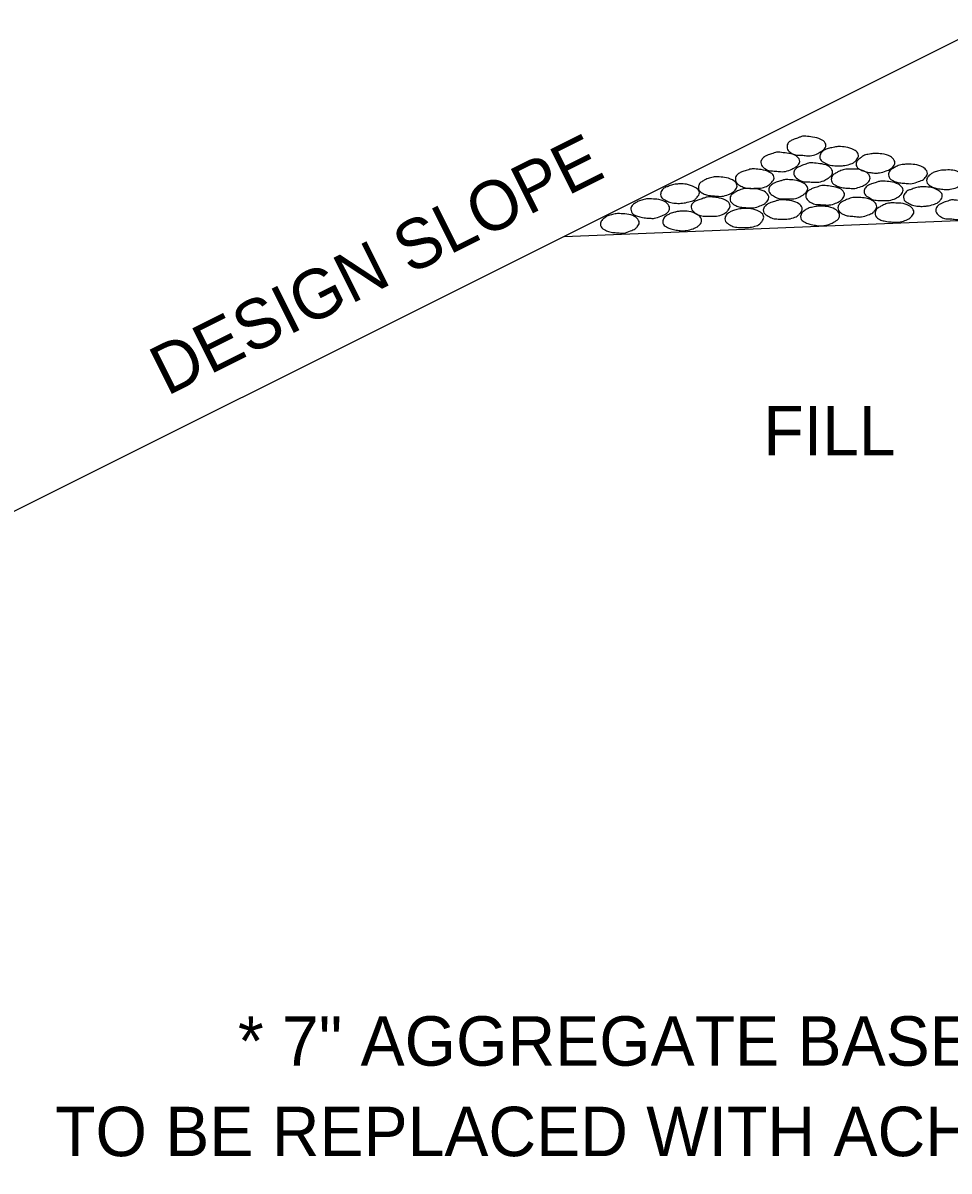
# Model space of a CAD drawing. Extents: x 438659 to 573674, y 10724 to 98600.
# Drawn here: x 493788 to 497162, y 66360 to 70542 of the extents above; entities that cross this region are included whole.
import ezdxf

# ---------------------------------------------------------------- set-up
doc = ezdxf.new("R2010")
doc.units = 0
doc.layers.add('T_Vehicle Path Rt', color=7, linetype='Continuous')

msp = doc.modelspace()

# ---------------------------------------------------------------- linework, layer by layer
at = {"layer": 'T_Vehicle Path Rt'}
for p, q in [((493589.4, 68680.3), (497314.8, 70541.7)), ((495759.4, 69764.5), (503294.2, 70064.7))]:
    msp.add_line(p, q, dxfattribs=at)
for points in [[(496640.5, 70128.9), (496665.2, 70126), (496695.1, 70117.8), (496711.1, 70104.4), (496713.3, 70095.4), (496705.7, 70080.4), (496696, 70073.4), (496679.1, 70063.9), (496655.8, 70058.1), (496642.9, 70058.1), (496624.9, 70060), (496603.3, 70061.2), (496588.5, 70067.5), (496573.7, 70081.4), (496571.8, 70090.6), (496576.2, 70104.7), (496587.1, 70113.4), (496597.8, 70118.5), (496614.5, 70124.1), (496624.2, 70128.2), (496640.5, 70128.9)], [(496760.6, 70091.6), (496786.1, 70089.6), (496815.4, 70079.9), (496830, 70067), (496832.2, 70059.5), (496824.6, 70043), (496817.6, 70035.3), (496800.1, 70026.8), (496777.1, 70022.2), (496764.2, 70021.2), (496745.5, 70021.7), (496724.2, 70025.1), (496709.1, 70032.3), (496693.4, 70044), (496690.9, 70053.9), (496695.3, 70067), (496707.4, 70078), (496717.6, 70082.8), (496734.9, 70087.4), (496745.1, 70089.6), (496760.6, 70091.6)], [(496545.6, 70070.9), (496571.1, 70067.5), (496600, 70060.5), (496616, 70046.4), (496618.4, 70037.7), (496610.4, 70022.4), (496601.2, 70015.8), (496584.4, 70006.9), (496560.4, 70000.1), (496548.3, 70000.1), (496529.8, 70002.3), (496508.7, 70003.5), (496493.2, 70010), (496479.1, 70023.6), (496476.4, 70033.1), (496481.5, 70046.7), (496492.7, 70056.4), (496503.4, 70061.2), (496519.9, 70066.6), (496529.8, 70070), (496545.6, 70070.9)], [(496892.8, 70065.8), (496917.6, 70065.1), (496948.4, 70055.4), (496962.5, 70040.8), (496965.1, 70032.3), (496956.9, 70016.8), (496948.9, 70010), (496932.4, 70002.7), (496908.1, 69996), (496895, 69995), (496876.6, 69996.7), (496856.4, 70000.1), (496840.7, 70006.4), (496825.9, 70018.3), (496823.4, 70027.5), (496828.3, 70041.3), (496839.4, 70050.1), (496849.9, 70058.1), (496866.6, 70063.2), (496877.1, 70065.1), (496892.8, 70065.8)], [(496453.1, 70010), (496478.1, 70007.6), (496507.3, 69998.4), (496522.5, 69986), (496524.7, 69976.8), (496516.5, 69962), (496507.7, 69953.7), (496492.5, 69944.8), (496468.4, 69939.7), (496456.1, 69939.7), (496436.9, 69939.2), (496416, 69942.6), (496400, 69949.8), (496385.2, 69963.2), (496383.5, 69971.2), (496387.9, 69986.5), (496398.5, 69995), (496410.2, 70000.1), (496427.7, 70005.4), (496436.9, 70008.6), (496453.1, 70010)], [(496666.2, 70031.9), (496690.9, 70029), (496721, 70021.7), (496735.6, 70007.1), (496737.8, 69998.9), (496730.5, 69983.3), (496721.5, 69976.5), (496705.7, 69967.3), (496682, 69961.5), (496669.1, 69961.5), (496650.2, 69963.2), (496629.3, 69964.2), (496614, 69971.4), (496599, 69984.8), (496596.3, 69994), (496600.9, 70008.1), (496612.6, 70016.6), (496623.7, 70021.7), (496640.5, 70028), (496650.2, 70031.4), (496666.2, 70031.9)], [(496802.6, 70009.5), (496827.3, 70008.6), (496857.9, 69999.3), (496872, 69985), (496874.1, 69976.5), (496866.6, 69961), (496859.3, 69954.2), (496841.6, 69946), (496818.6, 69939.2), (496805.7, 69939.2), (496786.3, 69940.4), (496766.2, 69943.8), (496750.6, 69949.4), (496735.1, 69962.5), (496733.2, 69971.9), (496737, 69986), (496748.9, 69994.5), (496759.9, 70000.3), (496776.6, 70007.1), (496786.3, 70009.3), (496802.6, 70009.5)], [(497011.7, 70027.3), (497037.5, 70025.8), (497066.6, 70016.6), (497080.9, 70002.7), (497083.6, 69993.5), (497075.3, 69978.7), (497068.8, 69971.9), (497051, 69964.2), (497027.3, 69956.4), (497014.9, 69956.4), (496996.2, 69958.1), (496976.3, 69960.5), (496959.3, 69966.3), (496943.8, 69979.7), (496941.6, 69988.9), (496946.2, 70003), (496957.4, 70011.7), (496969, 70018.3), (496985.8, 70024.6), (496996.2, 70026.3), (497011.7, 70027.3)], [(497150.8, 70006.1), (497175.8, 70005.4), (497204.6, 69995), (497219.2, 69982.1), (497221.6, 69973.4), (497214.6, 69957.1), (497206.1, 69950.6), (497189.8, 69942.6), (497165.6, 69936), (497153.2, 69934.8), (497134.8, 69936.7), (497113.9, 69939.9), (497097.6, 69946), (497082.6, 69958.1), (497080.2, 69967.8), (497085, 69981.4), (497095.9, 69991.3), (497107.6, 69997.9), (497124.3, 70003), (497135, 70005.4), (497150.8, 70006.1)], [(496180.9, 69955.4), (496205.9, 69954.2), (496235, 69943.8), (496250.5, 69931.6), (496252.7, 69923.6), (496244.2, 69907.1), (496236.9, 69898.9), (496219.5, 69891.6), (496196.7, 69886), (496184.5, 69884.8), (496164.6, 69885.3), (496143.3, 69889.2), (496128.5, 69896.2), (496113.4, 69908.1), (496111.2, 69917.3), (496115.6, 69931.6), (496126.8, 69941.6), (496138.2, 69946.5), (496154.9, 69952), (496164.4, 69954.2), (496180.9, 69955.4)], [(496318.7, 69980.9), (496344.4, 69979.2), (496373.3, 69970), (496388.1, 69955.9), (496389.8, 69947.4), (496382.5, 69932.6), (496374.5, 69925.3), (496358, 69916.8), (496334.2, 69910.3), (496321.6, 69910.3), (496302.9, 69912.2), (496282.8, 69914.2), (496266.5, 69920), (496251, 69933.3), (496249.1, 69943.1), (496253.2, 69956.4), (496264.4, 69965.4), (496275.5, 69971.9), (496293.2, 69977.8), (496302.9, 69980.2), (496318.7, 69980.9)], [(496574.2, 69971.4), (496599.5, 69969), (496629.8, 69960), (496644.8, 69946.5), (496647.5, 69938.2), (496639.5, 69922.7), (496631.3, 69916.1), (496613.5, 69905.9), (496590.7, 69900.8), (496577.6, 69900.8), (496558.7, 69901.3), (496538.1, 69903.5), (496522.5, 69911.5), (496507.7, 69923.9), (496505.6, 69933.8), (496510.4, 69947.4), (496521.8, 69956.4), (496532.5, 69961.5), (496548.3, 69966.3), (496558.5, 69970), (496574.2, 69971.4)], [(496923.4, 69965.6), (496948.9, 69963.4), (496977.3, 69954.2), (496992.1, 69940.9), (496994.3, 69933.1), (496987.2, 69916.6), (496979, 69909.6), (496962, 69900.3), (496938, 69894.8), (496925.8, 69894.8), (496907.4, 69895.3), (496886.5, 69897.7), (496870.5, 69905.4), (496854.7, 69917.8), (496852.3, 69928.5), (496857.4, 69941.6), (496868.6, 69950.8), (496879.7, 69955.4), (496896.5, 69961), (496908.1, 69964.4), (496923.4, 69965.6)], [(496434, 69938.7), (496458.2, 69937), (496488.6, 69928.5), (496503.6, 69913.9), (496505.6, 69905.4), (496498, 69890.4), (496490.5, 69883.4), (496473, 69875.1), (496450, 69868.3), (496436.4, 69868.3), (496417.5, 69869.5), (496396.9, 69872.4), (496381.6, 69878.3), (496366.3, 69891.6), (496364.1, 69900.8), (496368.7, 69914.7), (496380.1, 69923.6), (496391, 69929.7), (496407.8, 69936), (496417.5, 69938.2), (496434, 69938.7)], [(496710.4, 69949.8), (496735.1, 69946.5), (496764.2, 69938.7), (496779, 69924.6), (496781.2, 69916.1), (496773.4, 69900.8), (496766.2, 69893.8), (496748.9, 69884.8), (496725.6, 69878.8), (496712.5, 69878.8), (496694.1, 69880), (496672.7, 69881.7), (496656.7, 69889.2), (496642.2, 69902.3), (496640, 69912), (496643.9, 69925.1), (496655.3, 69934.1), (496666.9, 69939.7), (496684.4, 69945.2), (496694.1, 69948.9), (496710.4, 69949.8)], [(497066.1, 69944.8), (497090.8, 69943.5), (497120.7, 69933.3), (497135.2, 69920.5), (497137.4, 69912.7), (497129.9, 69895.7), (497122.6, 69888.5), (497104.9, 69880.4), (497081.6, 69875.1), (497069.2, 69873.9), (497050.3, 69874.1), (497029, 69878), (497013.9, 69885.3), (496998.9, 69896.7), (496996.2, 69907.1), (497000.8, 69920.5), (497011.7, 69930.9), (497023.6, 69935.5), (497040.1, 69940.9), (497049.8, 69943.5), (497066.1, 69944.8)], [(496072.4, 69900.8), (496097.2, 69899.4), (496127.3, 69890.6), (496141.8, 69875.8), (496144, 69867.8), (496136.7, 69851.8), (496128.7, 69845.3), (496112, 69838), (496088.4, 69830.2), (496075.6, 69830.2), (496056.2, 69831.7), (496035.5, 69835.3), (496020, 69840.4), (496005, 69853.3), (496003, 69863.2), (496007.1, 69876.8), (496019, 69885.8), (496030.2, 69892.3), (496046.7, 69897.9), (496056.2, 69900.3), (496072.4, 69900.8)], [(496294.2, 69908.1), (496318.5, 69905.4), (496347.1, 69896.2), (496362.2, 69883.4), (496364.1, 69874.6), (496357.3, 69859.6), (496349, 69851.1), (496332.8, 69842.6), (496308, 69838), (496295.7, 69838), (496276.5, 69838.2), (496255.9, 69840.2), (496240.1, 69847.4), (496225.3, 69861), (496222.4, 69870.5), (496227.2, 69884.3), (496238.2, 69892.8), (496250, 69897.7), (496266.8, 69903), (496277.2, 69906.7), (496294.2, 69908.1)], [(496556.8, 69897.7), (496581.3, 69894.8), (496610.4, 69886), (496624.9, 69872.7), (496627.1, 69864.7), (496620.3, 69849.4), (496612.6, 69841.1), (496595.6, 69832.2), (496571.6, 69827.1), (496558.7, 69827.1), (496539.8, 69827.6), (496519.9, 69830), (496503.6, 69838), (496487.8, 69850.1), (496485.4, 69860.6), (496490.5, 69873.4), (496502.2, 69882.9), (496513.1, 69888), (496529.8, 69892.8), (496540.5, 69896.2), (496556.8, 69897.7)], [(496691.9, 69873.9), (496716.2, 69873.2), (496746.5, 69863.2), (496760.6, 69850.1), (496763.3, 69841.6), (496756, 69825.1), (496747.5, 69819.1), (496732, 69811.1), (496707.4, 69803.8), (496694.3, 69802.6), (496675.4, 69804.7), (496655.3, 69808.4), (496639, 69814.9), (496623.7, 69826.3), (496621.3, 69836.3), (496626.2, 69849.9), (496637.8, 69860.1), (496648.7, 69866.4), (496665.7, 69871), (496675.7, 69873.2), (496691.9, 69873.9)], [(496827.8, 69906.4), (496852.8, 69904.5), (496882.4, 69894.8), (496896.5, 69881.4), (496898.9, 69872.4), (496890.9, 69857.6), (496884.3, 69850.6), (496867.1, 69843.1), (496843.3, 69835.3), (496830.5, 69835.3), (496811.5, 69837.5), (496791.2, 69839.7), (496775.4, 69845.3), (496759.4, 69858.9), (496757.4, 69868.3), (496762, 69881.7), (496773.4, 69891.1), (496784.9, 69896.7), (496801.6, 69903), (496811.5, 69905.4), (496827.8, 69906.4)], [(496961.7, 69886), (496987, 69884.8), (497017.1, 69875.6), (497031.6, 69861.3), (497034.1, 69852.8), (497026.3, 69838), (497019, 69830.7), (497001.5, 69822.2), (496978.2, 69816.1), (496965.4, 69816.1), (496946.2, 69817.4), (496925.3, 69820.5), (496910.3, 69825.6), (496894.5, 69839), (496892.6, 69848.4), (496897, 69861.8), (496908.8, 69871), (496919.5, 69877.1), (496936, 69883.8), (496946.2, 69885.8), (496961.7, 69886)], [(497182.1, 69896.7), (497208.3, 69894), (497237.4, 69886.5), (497252.9, 69872.2), (497255.6, 69864.2), (497247.8, 69848.4), (497239.3, 69841.6), (497221.4, 69832.2), (497198.6, 69826.3), (497186, 69826.3), (497167, 69828), (497145.7, 69829), (497130.4, 69837), (497116.1, 69849.9), (497113.6, 69859.6), (497118.3, 69872.7), (497129.4, 69881.9), (497139.9, 69887), (497157.1, 69892.8), (497166.8, 69896.7), (497182.1, 69896.7)], [(495961.5, 69847.4), (495988, 69845.3), (496016.6, 69837), (496030.9, 69822.2), (496033.4, 69814.4), (496025.8, 69798.9), (496018.6, 69792.4), (496001.3, 69784.1), (495977.5, 69776.6), (495964.9, 69776.6), (495946, 69778), (495925.9, 69780.5), (495910.1, 69787), (495894.6, 69799.6), (495892.1, 69809.6), (495897, 69822.7), (495907.7, 69832.2), (495918.8, 69839), (495936.3, 69844.5), (495946, 69846.5), (495961.5, 69847.4)], [(496189.6, 69855.9), (496214.6, 69855), (496243.7, 69844.5), (496257.8, 69831.7), (496260.7, 69822.7), (496253.2, 69806.7), (496245.2, 69799.6), (496229.4, 69792.4), (496204.9, 69785.8), (496192.1, 69784.4), (496173.4, 69786.8), (496153.2, 69790.2), (496136.7, 69796.7), (496121.2, 69808.1), (496119, 69817.8), (496123.4, 69831.2), (496135.3, 69841.1), (496146.2, 69847.4), (496162.7, 69852.3), (496173.9, 69855), (496189.6, 69855.9)], [(496415.3, 69866.4), (496440.3, 69864.7), (496470.9, 69854.5), (496484.9, 69842.1), (496486.9, 69834.6), (496479.6, 69817.8), (496472.3, 69809.6), (496454.4, 69801.1), (496431.3, 69797), (496418.7, 69796.2), (496400, 69796.7), (496378.4, 69799.4), (496363.4, 69806.7), (496348.1, 69819.1), (496345.7, 69828.3), (496350.5, 69842.1), (496361.7, 69851.8), (496373.1, 69857.2), (496389.1, 69862.2), (496399.5, 69864.7), (496415.3, 69866.4)]]:
    msp.add_spline(points, degree=3, dxfattribs=at)

# ---------------------------------------------------------------- texts
msp.add_text('DESIGN SLOPE', height=180, rotation=26.565, dxfattribs=at).set_placement((494312.6, 69181.7))
for s, p in [('FILL', (496485.7, 68967)), ('* 7" AGGREGATE BASE COURSE (CLASS 7)', (494571.6, 66744)), ('TO BE REPLACED WITH ACHM BASE COURSE (1-', (493905.6, 66414.5))]:
    msp.add_text(s, height=180, dxfattribs=at).set_placement(p)

doc.saveas('drawing.dxf')
